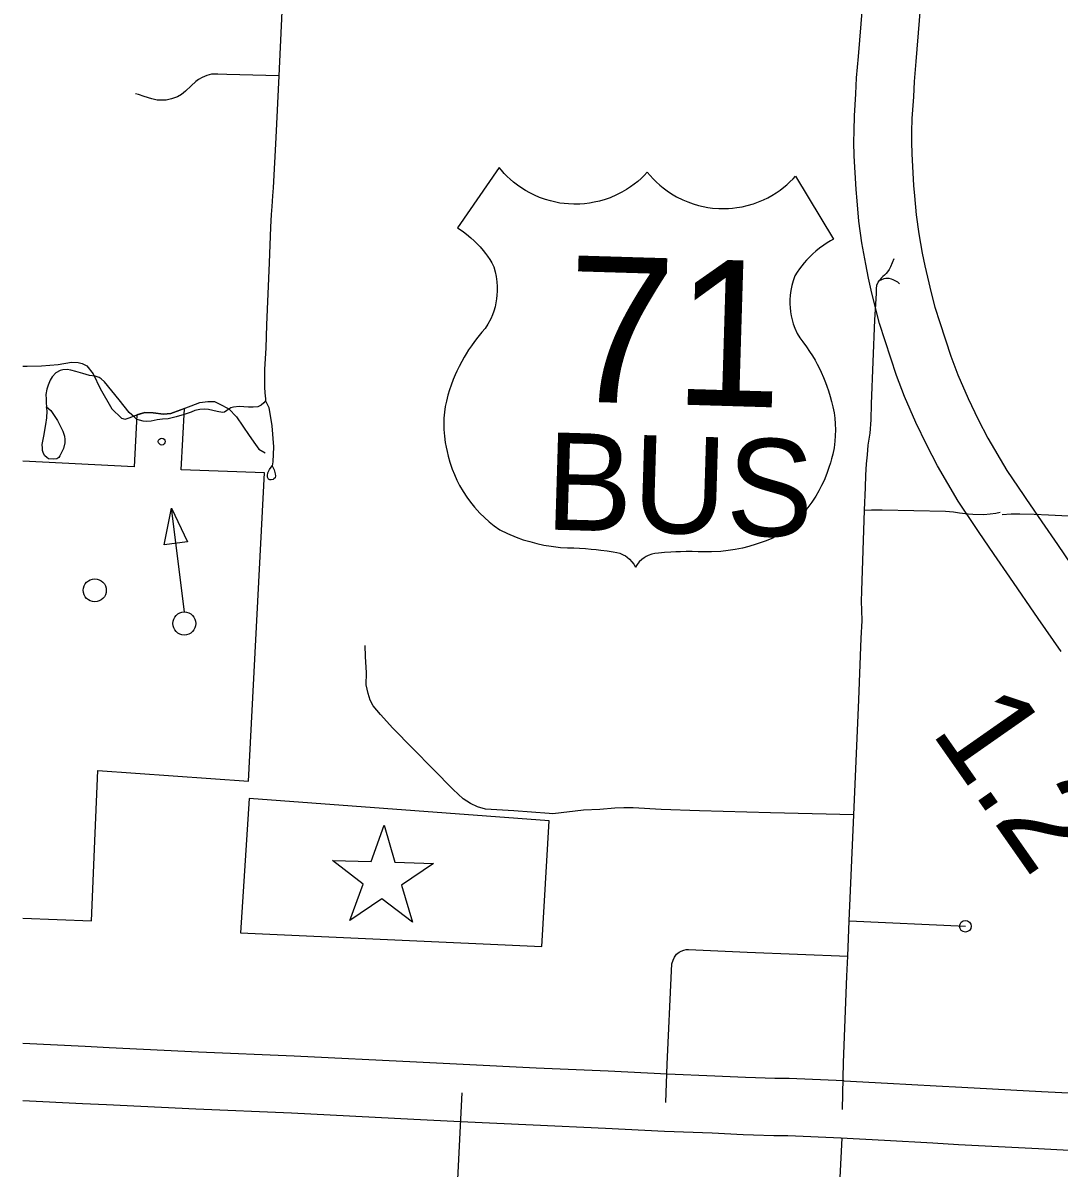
# Model space of a CAD drawing. Extents: x 653372 to 905732, y 627442 to 787275.
# Drawn here: x 654512 to 659009, y 743689 to 748661 of the extents above; entities that cross this region are included whole.
import ezdxf

# ---------------------------------------------------------------- set-up
doc = ezdxf.new("R2010")
doc.units = 0
for name, color, linetype in [('10', 7, 'Continuous'), ('15', 7, 'Continuous'), ('22', 7, 'Continuous'), ('33', 7, 'Continuous'), ('35', 7, 'Continuous'), ('48', 7, 'Continuous'), ('56', 7, 'Continuous'), ('57', 7, 'Continuous'), ('6', 7, 'Continuous')]:
    doc.layers.add(name, color=color, linetype=linetype)

msp = doc.modelspace()

# ---------------------------------------------------------------- linework, layer by layer
at = {"layer": '10'}
for points in [[(654511.7, 744231), (654782.1, 744217.8), (654886.1, 744212.7), (655273.5, 744194.4), (655689.4, 744176.7), (656220.4, 744150.3), (656422.5, 744140.2), (656738.6, 744125), (657051.9, 744110.7), (657307.5, 744098.1), (657514.5, 744089.9), (657648.5, 744083.4), (657691.9, 744081.7), (657775.9, 744079.1), (657837.3, 744078.8), (658074.1, 744068.7)], [(658075.8, 744068.6), (658264.5, 744058), (658475.4, 744046.7), (658586.6, 744040), (658932.6, 744021.7), (659197.9, 744008.3), (659407.2, 743999.1), (659488, 743995.2), (659938.1, 743973.8), (660260.8, 743957.6), (660422.5, 743949.8), (660482.1, 743946.6), (660654.6, 743940.8)], [(658063.5, 743818.9), (657831.3, 743828.8), (657771.5, 743829.2), (657683.1, 743831.8), (657637.3, 743833.7), (657503.5, 743840.2), (657296.4, 743848.4), (657040.1, 743861), (656727, 743875.3), (656410.2, 743890.5), (656207.9, 743900.7), (655677.8, 743927), (655262.3, 743944.7), (654874.1, 743963), (654769.9, 743968.1), (654511.7, 743980.7)], [(660654.6, 743940.8), (660643, 743691.1), (660409.6, 743700.2), (660248.6, 743707.9), (659925.9, 743724), (659476, 743745.4), (659395.6, 743749.3), (659186, 743758.6), (658919.7, 743772), (658572.4, 743790.4), (658461.2, 743797.1), (658250.8, 743808.4), (658061.8, 743819)]]:
    msp.add_lwpolyline(points, dxfattribs=at)
at = {"layer": '15'}
for points in [[(658169.5, 747613.4), (658152.7, 747706.2), (658140, 747800.1), (658132.1, 747889.1), (658128.3, 747937.1), (658119.2, 748084.5), (658118.7, 748143.4), (658119, 748192.6), (658120.7, 748257.2), (658126.9, 748352.9), (658129.9, 748422.5), (658137.6, 748514.7), (658190, 749155.5), (658194, 749210.5), (658195.5, 749228.3), (658221.9, 749505.7), (658221.9, 749513.2), (658239.4, 749740.3), (658240.2, 749748.2), (658245.2, 749818.9), (658256.3, 750008.7), (658274.8, 750558), (658275.6, 750571.3), (658525.2, 750556.5)], [(658525.2, 750556.5), (658524.6, 750546.4), (658506.1, 749997.2), (658494.7, 749802.8), (658489.4, 749727.3), (658488.5, 749718.6), (658471.9, 749504.1), (658471.9, 749494.5), (658444.5, 749206), (658443.3, 749191), (658439.3, 749136.2), (658386.7, 748494), (658379.4, 748406.7), (658376.5, 748339.5), (658370.5, 748245.9), (658369, 748188.6), (658368.7, 748143.7), (658369.1, 748093.2), (658377.7, 747954.6), (658381.2, 747910), (658388.5, 747827.9), (658399.7, 747745.2), (658414.9, 747661.3)], [(658414.9, 747661.3), (658426.4, 747605.9), (658437.6, 747556.7), (658453.2, 747488.5), (658469.2, 747427.1), (658491.4, 747359.6), (658539.3, 747214), (658570.1, 747132.8), (658614.4, 747029.9), (658658.2, 746939.6), (658699.8, 746858.8), (658782.4, 746717.3), (658855.2, 746608.7), (658864.1, 746596.6), (658933.3, 746494.8), (659001.6, 746395.8), (659123.3, 746216.8)], [(659017.4, 745931.8), (658917.5, 746074.9), (658795.3, 746254.5), (658727, 746353.5), (658659.7, 746452.6), (658650.4, 746465.3), (658570.4, 746584.6), (658480.6, 746738.5), (658434.5, 746827.9), (658387.1, 746925.8), (658338.3, 747039), (658303.6, 747130.6), (658253.9, 747281.4), (658229.2, 747356.6), (658210.4, 747429.1), (658193.8, 747501.1), (658182.1, 747552.8), (658169.5, 747613.4)]]:
    msp.add_lwpolyline(points, dxfattribs=at)
at = {"layer": '22'}
for points in [[(657221.6, 748013), (657208, 747998.6), (657195, 747986.1), (657180.4, 747973.1), (657164.5, 747960.4), (657149.3, 747949.3), (657130.9, 747937.2), (657111.1, 747925.7), (657088.7, 747914.2), (657060.3, 747902.1), (657038.6, 747894.4), (657014.1, 747887.3), (656991.7, 747882.1), (656971.1, 747878.5), (656949.4, 747875.8), (656929.5, 747874.4), (656902.2, 747873.9), (656880.1, 747874.9), (656860.9, 747876.6), (656842.7, 747879.1), (656824.2, 747882.5), (656801, 747887.9), (656779.6, 747894.2), (656753.5, 747903.5), (656731.5, 747913), (656711.6, 747922.9), (656693.3, 747933.2), (656676.5, 747943.7), (656657.7, 747956.9), (656640.6, 747970.3), (656625.8, 747983.1), (656613.4, 747994.8), (656600.8, 748007.7), (656588.4, 748021.6), (656578.5, 748033.7), (656397.4, 747771.4), (656409.5, 747763.6), (656424, 747753.6), (656437.6, 747743.3), (656455.8, 747728.2), (656470.2, 747715), (656483, 747702.3), (656496, 747688.3), (656509.3, 747672.6), (656518.8, 747660.4), (656528.1, 747647.6), (656537.5, 747633.6), (656546.7, 747618.8), (656555, 747601.5), (656561.1, 747580.5), (656565.6, 747559.6), (656568.7, 747537.4), (656570.2, 747516.9), (656570.3, 747497), (656569.3, 747478.5), (656567.6, 747463.7), (656564.6, 747445.6), (656560.7, 747428.5), (656555.4, 747410.1), (656549.6, 747394), (656542, 747375.9), (656530, 747352.7), (656517.9, 747334.5), (656503.5, 747318.2), (656485.9, 747297), (656471.6, 747278.3), (656458.2, 747259.7), (656445.9, 747241.3), (656435.5, 747224.8), (656426.3, 747209.4), (656416, 747191), (656404.9, 747169.5), (656394.8, 747148.4), (656387.9, 747132.7), (656379.6, 747112.6), (656370.4, 747088), (656363.1, 747067.4), (656356.2, 747045), (656349.6, 747018.9), (656345, 746995.7), (656341.5, 746971.4), (656339.1, 746944.8), (656338.2, 746919.8), (656338.6, 746895.3), (656340.8, 746866.5), (656344.4, 746839.2), (656348.2, 746818.4), (656352.4, 746800.3), (656357.7, 746779.7), (656364.9, 746754), (656375.4, 746722.9), (656384.6, 746699.9), (656395.3, 746676.2), (656407.2, 746653), (656422.6, 746626.2), (656438.7, 746601.5), (656454.4, 746580), (656472.3, 746557.9), (656495.5, 746532.4), (656515.2, 746513), (656535.6, 746494.9)], [(657221.6, 748013), (657234.3, 747997.8), (657246.4, 747984.6), (657260.3, 747970.7), (657275.4, 747957.1), (657289.9, 747945.1), (657307.6, 747931.9), (657326.6, 747919.2), (657348.3, 747906.4), (657375.9, 747892.6), (657397.1, 747883.6), (657421.2, 747875), (657443.2, 747868.6), (657463.6, 747863.7), (657485.1, 747859.8), (657504.9, 747857.1), (657532, 747855), (657554.1, 747854.6), (657573.4, 747855.2), (657591.8, 747856.6), (657610.4, 747858.9), (657633.9, 747862.9), (657655.6, 747867.9), (657682.2, 747875.7), (657704.8, 747883.8), (657725.3, 747892.5), (657744.1, 747901.6), (657761.5, 747911.1), (657781.1, 747923.1), (657798.9, 747935.5), (657814.4, 747947.4), (657827.5, 747958.3), (657840.9, 747970.5), (657854.1, 747983.6), (657864.8, 747995.1), (658029.8, 747722.4), (658017.2, 747715.4), (658002.2, 747706.2), (657987.9, 747696.7), (657968.9, 747682.8), (657953.7, 747670.4), (657940.2, 747658.5), (657926.4, 747645.3), (657912.2, 747630.5), (657902, 747618.9), (657891.9, 747606.6), (657881.6, 747593.2), (657871.6, 747579), (657862.2, 747562.3), (657854.9, 747541.6), (657849.2, 747521.1), (657844.7, 747499.1), (657842, 747478.7), (657840.7, 747458.9), (657840.6, 747440.4), (657841.4, 747425.4), (657843.3, 747407.2), (657846.2, 747389.9), (657850.4, 747371.2), (657855.2, 747354.8), (657861.7, 747336.3), (657872.3, 747312.4), (657883.3, 747293.5), (657896.7, 747276.4), (657912.9, 747254.1), (657926.1, 747234.7), (657938.4, 747215.2), (657949.6, 747196.2), (657959, 747179.1), (657967.2, 747163.1), (657976.4, 747144.1), (657986.2, 747122), (657995, 747100.4), (658000.9, 747084.3), (658008, 747063.7), (658015.7, 747038.5), (658021.7, 747017.6), (658027.3, 746994.8), (658032.3, 746968.4), (658035.5, 746944.9), (658037.6, 746920.4), (658038.4, 746893.8), (658037.7, 746868.8), (658035.9, 746844.4), (658032, 746815.7), (658026.7, 746788.7), (658021.7, 746768.2), (658016.4, 746750.3), (658009.9, 746730.1), (658001.2, 746704.9), (657988.8, 746674.4), (657978.3, 746652), (657966.2, 746629.1), (657952.9, 746606.5), (657935.9, 746580.7), (657918.3, 746557.1), (657901.4, 746536.6), (657882.2, 746515.6), (657857.5, 746491.5), (657836.7, 746473.3), (657815.3, 746456.5)], [(656535.6, 746494.9), (656556.8, 746477.8), (656582.3, 746460), (656614.6, 746444.4), (656652.5, 746428.5), (656683.4, 746417.4), (656711.3, 746408.8), (656742.9, 746400.5), (656772.6, 746394.1), (656804.6, 746388.7), (656844.9, 746384), (656875.9, 746382), (656902.4, 746381.3), (656928.1, 746380.3), (656953.8, 746378.7), (656978.2, 746376.8), (656999.5, 746374.7), (657020.5, 746372.3), (657047.2, 746368.7), (657073.4, 746364.6), (657089.1, 746361.9), (657102.1, 746359), (657117.6, 746352), (657126.5, 746346.7), (657134.2, 746341.3), (657144.7, 746332.3), (657154.7, 746321.5), (657162.8, 746310.5), (657170.1, 746297.8)], [(657815.3, 746456.5), (657793.1, 746440.7), (657766.5, 746424.5), (657733.3, 746410.8), (657694.6, 746397.2), (657663, 746388), (657634.6, 746381), (657602.6, 746374.7), (657572.6, 746370.1), (657540.3, 746366.6), (657499.8, 746364.3), (657468.8, 746364.2), (657442.3, 746365.1), (657416.6, 746365.6), (657390.8, 746365.6), (657366.3, 746365.1), (657344.9, 746364.3), (657323.9, 746363.2), (657296.9, 746361.2), (657270.6, 746358.7), (657254.7, 746357), (657241.6, 746354.8), (657225.7, 746348.8), (657216.5, 746344), (657208.5, 746339.1), (657197.4, 746330.7), (657186.8, 746320.5), (657178.1, 746310), (657170.1, 746297.8)]]:
    msp.add_lwpolyline(points, dxfattribs=at)
at = {"layer": '33'}
for points in [[(655667, 749334.5), (655660.5, 749216.8), (655651.5, 749024.3), (655635.8, 748710.6), (655622.3, 748431.2), (655609.9, 748162.9), (655597.6, 747945.6), (655595.6, 747909.7), (655591.5, 747863.6), (655588.7, 747829.5), (655586.1, 747774.3), (655580.6, 747618.8), (655568.9, 747350.2), (655565.9, 747248.5), (655560.4, 747157), (655560, 747112.5), (655559.5, 747080.2), (655561.4, 747055.4), (655564.2, 747029.6)], [(655622.3, 748431.2), (655396.5, 748437.7), (655358.2, 748438.9), (655329.9, 748438.5), (655310.3, 748433.1), (655289.1, 748424.3), (655273.9, 748415.7), (655262.1, 748406.1), (655241.6, 748387.8), (655217.8, 748364.1), (655200.4, 748349.6), (655182.1, 748340.7), (655156.4, 748331), (655132.9, 748325.7), (655108, 748325), (655094.4, 748325.9), (655071.8, 748331), (655038.6, 748342), (655012.8, 748349.9), (655000.7, 748352.9)], [(658292.2, 747637.3), (658277.4, 747601.9), (658270.8, 747591), (658264.2, 747580), (658259.1, 747573.2), (658251.2, 747565.4), (658243.4, 747559.4), (658237.2, 747552.9), (658229.6, 747543), (658239.2, 747547.6), (658249, 747551.2), (658257.1, 747552.7), (658270.6, 747552.3), (658279.6, 747550.3), (658286.6, 747547.6), (658298.6, 747540.9), (658307.5, 747536.5), (658315.7, 747528.9)], [(658068.8, 743943.8), (658073.9, 744147.4), (658087.3, 744521.9), (658092, 744609), (658098.4, 744762.6), (658118.1, 745222.8), (658140, 745722), (658149.5, 745989.4), (658153.8, 746065.2), (658152.4, 746111.3), (658151.5, 746149.7), (658152.2, 746195.1), (658164.8, 746545.2), (658168.4, 746644.5), (658170.7, 746697.5), (658172.9, 746746.3), (658176.9, 746785.2), (658180.2, 746827.7), (658188.8, 746880.5), (658192.6, 746937.6), (658195.4, 747006.6), (658209.6, 747371.6), (658216, 747485.9), (658216.6, 747506.1), (658218.5, 747522.1), (658223.1, 747535.2), (658229.6, 747543)], [(655564.2, 747029.6), (655564.4, 747020.4), (655557.9, 747011.6), (655546.3, 747001.6), (655531.7, 746994.4), (655511, 746992.3), (655490.8, 746992.9), (655450.9, 746995), (655425.7, 746992.6), (655414.8, 746989.8), (655397.3, 746977.7), (655386.4, 746971.3), (655378.2, 746969.8), (655354.5, 746973.2), (655317.5, 746982.8), (655299.6, 746984.3), (655278.9, 746982.2), (655258.5, 746978.3), (655241.7, 746971.6), (655212.2, 746961.3), (655177.1, 746950.2), (655142.7, 746942.2), (655117.1, 746940.3), (655094.5, 746937.8), (655068.7, 746932.3), (655049.4, 746930.7), (655033.2, 746931.6), (655017.2, 746935.7), (655005.6, 746939.6), (654996.5, 746949.3), (654973.2, 746968.9), (654929.5, 747024.1), (654865.4, 747103.1), (654851, 747115.7), (654842.1, 747120.9), (654825.2, 747127.3), (654801.1, 747130.7), (654771.7, 747138.3), (654741.4, 747148.2), (654720, 747153.8), (654703.5, 747156.1), (654685, 747155.3), (654672.8, 747152.1), (654655, 747142.3), (654638.7, 747123.9), (654629.8, 747110.2), (654621, 747088.5), (654615.5, 747070.2), (654611.7, 747048.3), (654612, 747027.6), (654612.4, 747011.4), (654614.6, 746993.8)], [(655564.4, 747020.4), (655578.7, 746991.9), (655592.7, 746912.3), (655599.6, 746820.3), (655596.7, 746755.7), (655593.3, 746738.4)], [(654614.6, 746993.8), (654632.8, 746977.7), (654661.5, 746934.4), (654685.2, 746889.2), (654691.8, 746866.8), (654694.3, 746852.7), (654694.3, 746837.7), (654688.3, 746812.8), (654671.8, 746780.9), (654667.5, 746774.8), (654658.6, 746768.8), (654643.4, 746767.3), (654623.2, 746768.9), (654615.2, 746774.4), (654607.2, 746781.4), (654600.9, 746791.6), (654596, 746804.8), (654596.5, 746814.1), (654595.6, 746830.6), (654602.5, 746866.1), (654611.7, 746917), (654615.5, 746946.9), (654616.4, 746977.3), (654614.6, 746993.8)], [(655593.3, 746738.4), (655601.5, 746720.7), (655607.2, 746703.9), (655608.4, 746694.4), (655606.2, 746685.8), (655601.2, 746681.4), (655597.3, 746678.4), (655589, 746676.6), (655583.7, 746677.1), (655577.5, 746679.8), (655573.4, 746688.5), (655572.9, 746695.8), (655574.7, 746707.8), (655581.2, 746722.5), (655593.3, 746738.4)], [(658164.8, 746545.2), (658194.3, 746547.5), (658240.8, 746547.3), (658515.6, 746540.9), (658550.5, 746538.1), (658576.7, 746534.2), (658613.7, 746530), (658634.7, 746528.2), (658681.6, 746526.8), (658710.4, 746529), (658733.8, 746533.2), (658752.8, 746537)], [(659049.6, 746519.8), (658963.6, 746523.4), (658901.3, 746526.2), (658838.3, 746527.6), (658812.5, 746527.8), (658800.4, 746527.6), (658761.9, 746524.6)], [(658118.1, 745222.8), (657756.5, 745231.5), (657447.8, 745240.8), (657281.7, 745245.8), (657160.2, 745253.5), (657120.4, 745253.7), (657080.6, 745251.8), (657016.2, 745245.6), (656944.7, 745242.6), (656811.2, 745227.8), (656795.4, 745228.8), (656642.8, 745239.5), (656520.1, 745247.8), (656484.7, 745257.4), (656454.6, 745271.6), (656422.5, 745291.9), (656378.9, 745333), (656116.7, 745598.9), (656063.4, 745658.2), (656031.9, 745695.8), (656019.4, 745720.7), (656010, 745749.5), (656002, 745786.5), (656002.5, 745839.5), (655999.2, 745910.1), (655996.9, 745958)], [(658098.4, 744762.6), (658602.2, 744738.9)], [(657302, 743973.2), (657307.6, 744140.9), (657327, 744545.6), (657328.6, 744576), (657333.5, 744591.8), (657340.4, 744605.4), (657348.7, 744617.5), (657359.9, 744625.9), (657368.7, 744630.7), (657379.8, 744635.4), (657390.7, 744638), (657400.2, 744638.4), (657654.5, 744626.5), (658092, 744609)], [(656416.3, 744015.3), (656387.6, 743438), (656354.8, 742667.5), (656342.2, 742307.3), (656325.8, 741966.1), (656323.9, 741873.8), (656318.6, 741843.2)], [(658066.6, 743818.8), (658041.5, 743334), (658016.9, 742728.3), (657998.8, 742245.6), (657990.7, 741998.4), (657977.8, 741661.9)]]:
    msp.add_lwpolyline(points, dxfattribs=at)
msp.add_circle((658602.2, 744738.9), 25, dxfattribs=at)
at = {"layer": '35'}
msp.add_lwpolyline([(654511.7, 747170.1), (654530.2, 747171.4), (654591.8, 747172.2), (654665.3, 747177.3), (654722.7, 747188.2), (654751.6, 747186.4), (654768.7, 747182.3), (654789.3, 747172.6), (654815.9, 747138), (654846.6, 747073.6), (654898.3, 746985.1), (654939.7, 746944.9), (654954.9, 746940.8), (654972.3, 746945.7), (655002.6, 746958.4), (655040.9, 746969.9), (655077.1, 746968.8), (655121.3, 746963), (655153.1, 746965.7), (655192.9, 746979.9), (655280, 747012.6), (655313.6, 747017.9), (655342.6, 747018), (655365.8, 747006.4), (655405, 746985.3), (655439.3, 746950.7), (655493, 746869.4), (655520.9, 746830.5), (655535.7, 746811), (655563.2, 746793.9)], dxfattribs=at)
at = {"layer": '56'}
for p, q in [((655125.2, 746395.7), (655157.1, 746553.8)), ((655157.1, 746553.8), (655226.4, 746408.2)), ((655226.4, 746408.2), (655125.2, 746395.7))]:
    msp.add_line(p, q, dxfattribs=at)
msp.add_lwpolyline([(655212.5, 746103.9), (655157.1, 746553.8)], dxfattribs=at)
for centre, radius in [((655114.4, 746843.4), 15), ((654823.7, 746197.5), 50), ((655212.1, 746053.4), 50)]:
    msp.add_circle(centre, radius, dxfattribs=at)
at = {"layer": '57'}
for points in [[(656155.5, 744917.1), (656202.5, 744756.1), (656069.8, 744858.7), (655931.2, 744764.2), (655987.8, 744922.1), (655855.1, 745024.8), (656022.8, 745019.7), (656079.4, 745177.6), (656126.4, 745016.6)], [(656126.4, 745016.6), (656294.1, 745011.6), (656155.5, 744917.1)]]:
    msp.add_lwpolyline(points, dxfattribs=at)
at = {"layer": '6'}
for points in [[(655212.9, 746987.4), (655153.1, 746965.7), (655121.3, 746963), (655077.1, 746968.8), (655040.9, 746969.9), (655006.2, 746959.9), (654994.1, 746733.4), (654511.7, 746757.8)], [(654511.7, 744774.3), (654808.9, 744762.3), (654826, 745143.6), (654836.2, 745415.5), (655491.4, 745368.5), (655559.9, 746708.2), (655198.2, 746720.8), (655212.9, 746987.4)]]:
    msp.add_lwpolyline(points, dxfattribs=at)
msp.add_lwpolyline([(655455.6, 744710), (656763.9, 744651.3), (656795.1, 745196), (655493.8, 745293.2)], close=True, dxfattribs=at)

# ---------------------------------------------------------------- texts
at = {"layer": '22'}
for s, height, p in [('71', 633.6, (656861, 747019)), ('BUS', 422.4, (656775.7, 746461.9))]:
    msp.add_text(s, height=height, rotation=358.28, dxfattribs=at).set_placement(p)
at = {"layer": '48'}
msp.add_text('1.2', height=422.4, rotation=304.9824, dxfattribs=at).set_placement((658448.7, 745584.4))

doc.saveas('drawing.dxf')
